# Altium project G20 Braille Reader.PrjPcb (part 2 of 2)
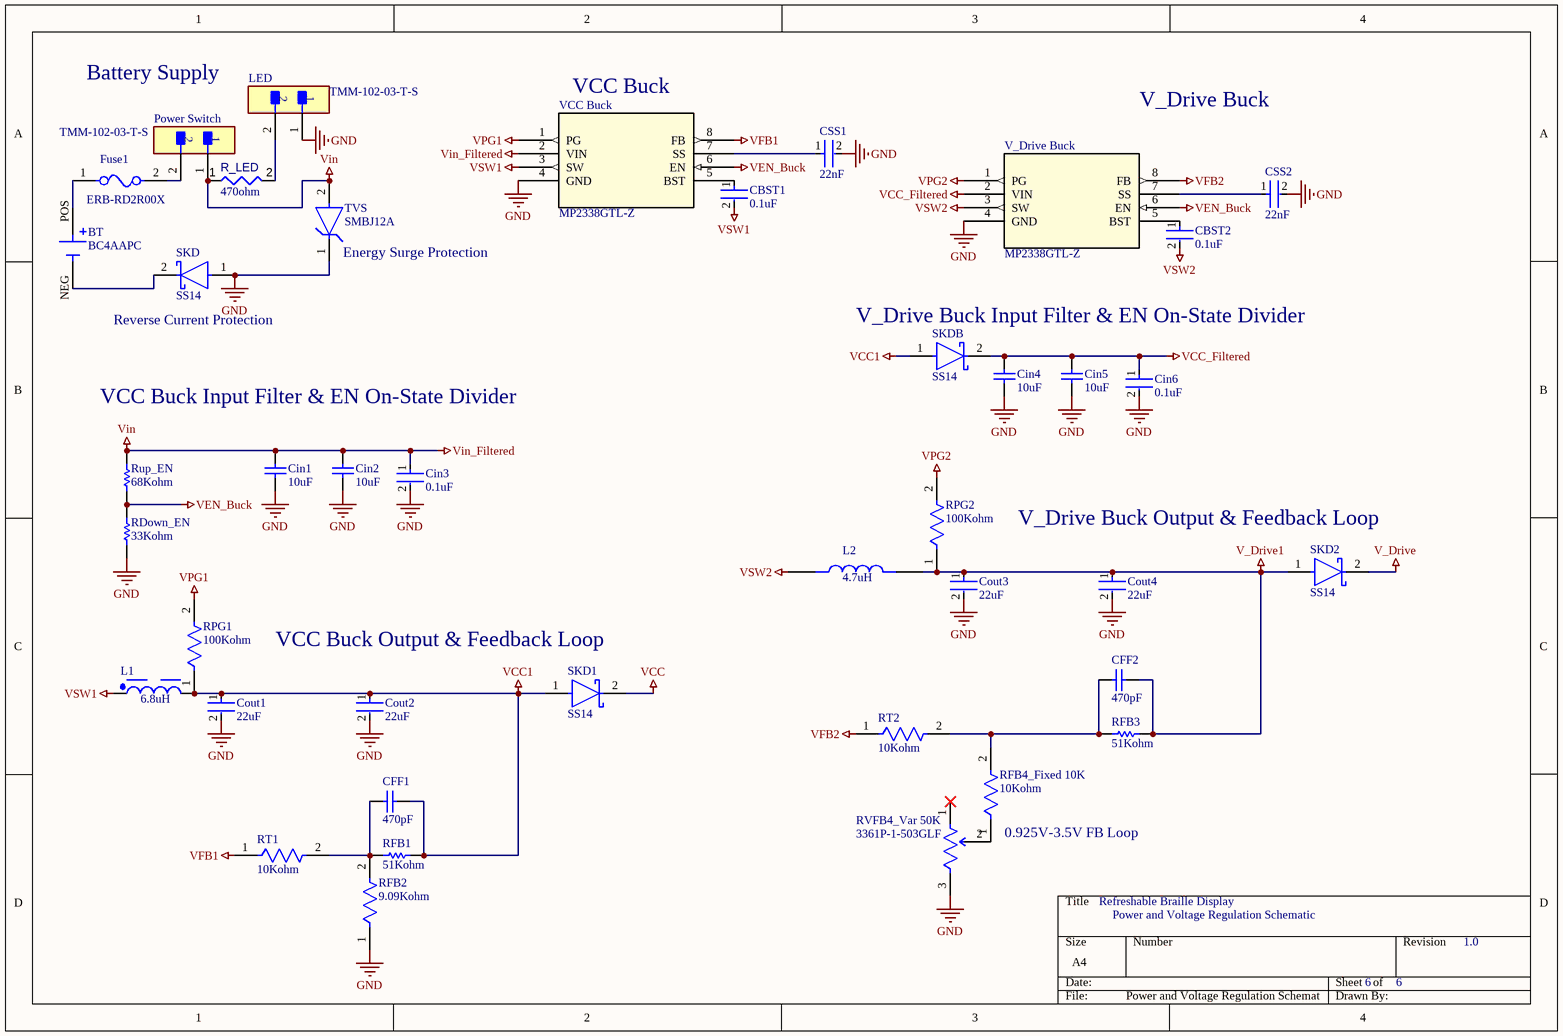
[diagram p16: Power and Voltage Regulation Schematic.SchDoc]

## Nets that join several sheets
GND: MCU Schematic (8 pins), Array 1 Cell Driving Schematic (20 pins), Array 2 Cell Driving Schematic (20 pins), Power and Voltage Regulation Schematic (20 pins)
V_Drive: Array 1 Cell Driving Schematic (A1_Reset_Source.9 A1_Set_Source.9 C5_D.2 C8_D.2), Array 2 Cell Driving Schematic (A2_Reset_Source.9 A2_Set_Source.9 C13_D.2 C16_D.2), Power and Voltage Regulation Schematic (SKD2.2)
VCC: MCU Schematic (5 pins), Array 1 Cell Driving Schematic (12 pins), Array 2 Cell Driving Schematic (12 pins), Power and Voltage Regulation Schematic (SKD1.2)
A1 Cell1: Array 1 Cell Driving Schematic (A1_Set_Sink.11), Array 1 Braille Cell Schematic (A1D7C1.2)
A1 Cell1 Reset: Array 1 Cell Driving Schematic (A1_Reset_Source.11), Array 1 Braille Cell Schematic (A1D7C1.1)
A1 Cell2: Array 1 Cell Driving Schematic (A1_Set_Sink.12), Array 1 Braille Cell Schematic (A1D7C2.2)
A1 Cell2 Reset: Array 1 Cell Driving Schematic (A1_Reset_Source.12), Array 1 Braille Cell Schematic (A1D7C2.1)
A1 Cell3: Array 1 Cell Driving Schematic (A1_Set_Sink.13), Array 1 Braille Cell Schematic (A1D7C3.2)
A1 Cell3 Reset: Array 1 Cell Driving Schematic (A1_Reset_Source.13), Array 1 Braille Cell Schematic (A1D7C3.1)
A1 Cell4: Array 1 Cell Driving Schematic (A1_Set_Sink.14), Array 1 Braille Cell Schematic (A1D7C4.2)
A1 Cell4 Reset: Array 1 Cell Driving Schematic (A1_Reset_Source.14), Array 1 Braille Cell Schematic (A1D7C4.1)
A1 Cell5: Array 1 Cell Driving Schematic (A1_Set_Sink.15), Array 1 Braille Cell Schematic (A1D7C5.2)
A1 Cell5 Reset: Array 1 Cell Driving Schematic (A1_Reset_Source.15), Array 1 Braille Cell Schematic (A1D7C5.1)
A1 Cell6: Array 1 Cell Driving Schematic (A1_Set_Sink.16), Array 1 Braille Cell Schematic (A1D7C6.2)
A1 Cell6 Reset: Array 1 Cell Driving Schematic (A1_Reset_Source.16), Array 1 Braille Cell Schematic (A1D7C6.1)
A1 Cell7: Array 1 Cell Driving Schematic (A1_Set_Sink.17), Array 1 Braille Cell Schematic (A1D7C7.2)
A1 Cell7 Reset: Array 1 Cell Driving Schematic (A1_Reset_Source.17), Array 1 Braille Cell Schematic (A1D7C7.1)
A1 Cell8: Array 1 Cell Driving Schematic (A1_Set_Sink.18), Array 1 Braille Cell Schematic (A1D7C8.2)
A1 Cell8 Reset: Array 1 Cell Driving Schematic (A1_Reset_Source.18), Array 1 Braille Cell Schematic (A1D7C8.1)
A1 Pin1: Array 1 Cell Driving Schematic (A1_Set_Source.18), Array 1 Braille Cell Schematic (8 pins)
A1 Pin1 Reset: Array 1 Cell Driving Schematic (A1_Reset_Sink.18), Array 1 Braille Cell Schematic (8 pins)
A1 Pin2: Array 1 Cell Driving Schematic (A1_Set_Source.17), Array 1 Braille Cell Schematic (8 pins)
A1 Pin2 Reset: Array 1 Cell Driving Schematic (A1_Reset_Sink.17), Array 1 Braille Cell Schematic (8 pins)
A1 Pin3: Array 1 Cell Driving Schematic (A1_Set_Source.16), Array 1 Braille Cell Schematic (8 pins)
A1 Pin3 Reset: Array 1 Cell Driving Schematic (A1_Reset_Sink.16), Array 1 Braille Cell Schematic (8 pins)
A1 Pin4: Array 1 Cell Driving Schematic (A1_Set_Source.15), Array 1 Braille Cell Schematic (8 pins)
A1 Pin4 Reset: Array 1 Cell Driving Schematic (A1_Reset_Sink.15), Array 1 Braille Cell Schematic (8 pins)
A1 Pin5: Array 1 Cell Driving Schematic (A1_Set_Source.14), Array 1 Braille Cell Schematic (8 pins)
A1 Pin5 Reset: Array 1 Cell Driving Schematic (A1_Reset_Sink.14), Array 1 Braille Cell Schematic (8 pins)
A1 Pin6: Array 1 Cell Driving Schematic (A1_Set_Source.13), Array 1 Braille Cell Schematic (8 pins)
A1 Pin6 Reset: Array 1 Cell Driving Schematic (A1_Reset_Sink.13), Array 1 Braille Cell Schematic (8 pins)
A2 Cell1: Array 2 Cell Driving Schematic (A2_Set_Sink.11), Array 2 Braille Cell Schematic (A2D7C1.2)
A2 Cell1 Reset: Array 2 Cell Driving Schematic (A2_Reset_Source.11), Array 2 Braille Cell Schematic (A2D7C1.1)
A2 Cell2: Array 2 Cell Driving Schematic (A2_Set_Sink.12), Array 2 Braille Cell Schematic (A2D7C2.2)
A2 Cell2 Reset: Array 2 Cell Driving Schematic (A2_Reset_Source.12), Array 2 Braille Cell Schematic (A2D7C2.1)
A2 Cell3: Array 2 Cell Driving Schematic (A2_Set_Sink.13), Array 2 Braille Cell Schematic (A2D7C3.2)
A2 Cell3 Reset: Array 2 Cell Driving Schematic (A2_Reset_Source.13), Array 2 Braille Cell Schematic (A2D7C3.1)
A2 Cell4: Array 2 Cell Driving Schematic (A2_Set_Sink.14), Array 2 Braille Cell Schematic (A2D7C4.2)
A2 Cell4 Reset: Array 2 Cell Driving Schematic (A2_Reset_Source.14), Array 2 Braille Cell Schematic (A2D7C4.1)
A2 Cell5: Array 2 Cell Driving Schematic (A2_Set_Sink.15), Array 2 Braille Cell Schematic (A2D7C5.2)
A2 Cell5 Reset: Array 2 Cell Driving Schematic (A2_Reset_Source.15), Array 2 Braille Cell Schematic (A2D7C5.1)
A2 Cell6: Array 2 Cell Driving Schematic (A2_Set_Sink.16), Array 2 Braille Cell Schematic (A2D7C6.2)
A2 Cell6 Reset: Array 2 Cell Driving Schematic (A2_Reset_Source.16), Array 2 Braille Cell Schematic (A2D7C6.1)
A2 Cell7: Array 2 Cell Driving Schematic (A2_Set_Sink.17), Array 2 Braille Cell Schematic (A2D7C7.2)
A2 Cell7 Reset: Array 2 Cell Driving Schematic (A2_Reset_Source.17), Array 2 Braille Cell Schematic (A2D7C7.1)
A2 Cell8: Array 2 Cell Driving Schematic (A2_Set_Sink.18), Array 2 Braille Cell Schematic (A2D7C8.2)
A2 Cell8 Reset: Array 2 Cell Driving Schematic (A2_Reset_Source.18), Array 2 Braille Cell Schematic (A2D7C8.1)
A2 Cell Select 0: MCU Schematic (MCU.14), Array 2 Cell Driving Schematic (A2_Cell_Reset_Decoder.1 A2_Cell_Set_Decoder.1)
A2 Cell Select 1: MCU Schematic (MCU.13), Array 2 Cell Driving Schematic (A2_Cell_Reset_Decoder.2 A2_Cell_Set_Decoder.2)
A2 Cell Select 2: MCU Schematic (MCU.12), Array 2 Cell Driving Schematic (A2_Cell_Reset_Decoder.3 A2_Cell_Set_Decoder.3)
A2 Pin1: Array 2 Cell Driving Schematic (A2_Set_Source.18), Array 2 Braille Cell Schematic (8 pins)
A2 Pin1 Reset: Array 2 Cell Driving Schematic (A2_Reset_Sink.18), Array 2 Braille Cell Schematic (8 pins)
A2 Pin2: Array 2 Cell Driving Schematic (A2_Set_Source.17), Array 2 Braille Cell Schematic (8 pins)
A2 Pin2 Reset: Array 2 Cell Driving Schematic (A2_Reset_Sink.17), Array 2 Braille Cell Schematic (8 pins)
A2 Pin3: Array 2 Cell Driving Schematic (A2_Set_Source.16), Array 2 Braille Cell Schematic (8 pins)
A2 Pin3 Reset: Array 2 Cell Driving Schematic (A2_Reset_Sink.16), Array 2 Braille Cell Schematic (8 pins)
A2 Pin4: Array 2 Cell Driving Schematic (A2_Set_Source.15), Array 2 Braille Cell Schematic (8 pins)
A2 Pin4 Reset: Array 2 Cell Driving Schematic (A2_Reset_Sink.15), Array 2 Braille Cell Schematic (8 pins)
A2 Pin5: Array 2 Cell Driving Schematic (A2_Set_Source.14), Array 2 Braille Cell Schematic (8 pins)
A2 Pin5 Reset: Array 2 Cell Driving Schematic (A2_Reset_Sink.14), Array 2 Braille Cell Schematic (8 pins)
A2 Pin6: Array 2 Cell Driving Schematic (A2_Set_Source.13), Array 2 Braille Cell Schematic (8 pins)
A2 Pin6 Reset: Array 2 Cell Driving Schematic (A2_Reset_Sink.13), Array 2 Braille Cell Schematic (8 pins)
A2 Pin Select 0: MCU Schematic (MCU.11), Array 2 Cell Driving Schematic (A2_Pin_Reset_Decoder.1 A2_Pin_Set_Decoder.1)
A2 Pin Select 1: MCU Schematic (MCU.10), Array 2 Cell Driving Schematic (A2_Pin_Reset_Decoder.2 A2_Pin_Set_Decoder.2)
A2 Pin Select 2: MCU Schematic (MCU.9), Array 2 Cell Driving Schematic (A2_Pin_Reset_Decoder.3 A2_Pin_Set_Decoder.3)
Cell Select 0: MCU Schematic (MCU.5), Array 1 Cell Driving Schematic (A1_Cell_Reset_Decoder.1 A1_Cell_Set_Decoder.1)
Cell Select 1: MCU Schematic (MCU.4), Array 1 Cell Driving Schematic (A1_Cell_Reset_Decoder.2 A1_Cell_Set_Decoder.2)
Cell Select 2: MCU Schematic (MCU.3), Array 1 Cell Driving Schematic (A1_Cell_Reset_Decoder.3 A1_Cell_Set_Decoder.3)
NetA1_Cell_Reset_Decoder_4: MCU Schematic (MCU.28), Array 1 Cell Driving Schematic (A1_Cell_Reset_Decoder.4 A1_Cell_Set_Decoder.6 A1_Pin_Reset_Decoder.4 A1_Pin_Set_Decoder.6)
NetA1_Cell_Reset_Decoder_6: MCU Schematic (MCU.2), Array 1 Cell Driving Schematic (A1_Cell_Reset_Decoder.6 A1_Cell_Set_Decoder.4 A1_Pin_Reset_Decoder.6 A1_Pin_Set_Decoder.4)
NetA2_Cell_Reset_Decoder_4: MCU Schematic (MCU.6), Array 2 Cell Driving Schematic (A2_Cell_Reset_Decoder.4 A2_Cell_Set_Decoder.6 A2_Pin_Reset_Decoder.4 A2_Pin_Set_Decoder.6)
NetA2_Cell_Reset_Decoder_6: MCU Schematic (MCU.15), Array 2 Cell Driving Schematic (A2_Cell_Reset_Decoder.6 A2_Cell_Set_Decoder.4 A2_Pin_Reset_Decoder.6 A2_Pin_Set_Decoder.4)
Pin Select 0: MCU Schematic (MCU.27), Array 1 Cell Driving Schematic (A1_Pin_Reset_Decoder.1 A1_Pin_Set_Decoder.1)
Pin Select 1: MCU Schematic (MCU.26), Array 1 Cell Driving Schematic (A1_Pin_Reset_Decoder.2 A1_Pin_Set_Decoder.2)
Pin Select 2: MCU Schematic (MCU.25), Array 1 Cell Driving Schematic (A1_Pin_Reset_Decoder.3 A1_Pin_Set_Decoder.3)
